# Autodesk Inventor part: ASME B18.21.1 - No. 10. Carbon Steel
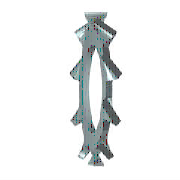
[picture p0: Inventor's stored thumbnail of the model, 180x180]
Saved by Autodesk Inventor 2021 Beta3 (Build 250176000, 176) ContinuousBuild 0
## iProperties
Created: 2013-02
Part Number: ASME B18.21.1 - No. 10. Carbon Steel
Material: Generic
Description: Lock Washers (Inch Series) External Tooth Lock Washer - Type A
Document SubType Name: Modeling
Standard: ASME B18.21.1
Designer: John
Standard Revision: 1999
Standards Organization: ANSI
Language: en-US
Size Designation: No. 10. Carbon Steel
Categories: <MemberInstance><Categories><Category DisplayName="Fasteners" InternalName="e4da775c-781d-43d5-af7c-5136215cf5a6" Mnemonic="FSTN"><Category DisplayName="Washers
Density: 1 g/cm^3
Appearance: Default
IsCustomPart: 0
Author: John
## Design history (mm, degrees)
sketch "Sketch1"
  geometry: C1 r 5.207 at (0, 0); C2 r 2.477 at (0, 0)
  constraints: 2 centre point, 1 coincident, 1 other
  dimensions: "d0" = 10.414 diameter of C1 (= SD2); "d1" = 4.953 diameter of C2 (= SD1)
extrude "Body" new body sketch "Sketch1" distance "d2" = 0.6096 (= SD); taper "d3" = 0 deg
sketch "Sketch2"
  geometry: L1 (0, 0)-(0, 5.207); L2 (-0.749, 3.768)-(-1.016, 5.107); L3 (0.749, 3.768)-(1.016, 5.107); L4 (-0.749, 3.768)-(0, 0); L5 (0, 0)-(0.749, 3.768); A1 r 5.207 centre (0, 0) between (0, 5.207) and (1.016, 5.107) reference; A2 r 5.207 centre (0, 0) between (1.016, 5.107) and (-1.016, 5.107); A3 r 3.842 centre (0, 0) between (0.749, 3.768) and (-0.749, 3.768)
  constraints: 10 end point, 7 point on circle, 2 centre point, 2 coincident, 2 collinear, 1 concentric, 1 symmetric about line, 1 vertical
  dimensions: "d4" = 22.5 deg angle of L3 L2 (computed from SAZ); "d5" = 7.6835 diameter of A3 (= 0.5 x SD2 + 0.5 x SD1)
extrude "Cut" cut sketch "Sketch2" extent not by distance; stored distance "d6" = 0.6096 (= SD); taper "d7" = 0 deg
pattern_circular "Cuts" dims angle "d11" = 360 deg
workaxis "Work Axis1"
workplane "Work Plane1"
body "Solid1"
fillet "Fillet1" dims "d8" = 0.15621 (= 0.015 x SD2)
other parameters: "SD" = 0.6096 [user parameter; used in 2 equation terms], "SD1" = 4.953 [user parameter; used in 2 equation terms], "SD2" = 10.414 [user parameter; used in 3 equation terms], "NND" = 4.826 [user parameter], "d12" = 0, "d13" = 0, "d14" = 0, "d15" = 0, "d16" = 90 deg
